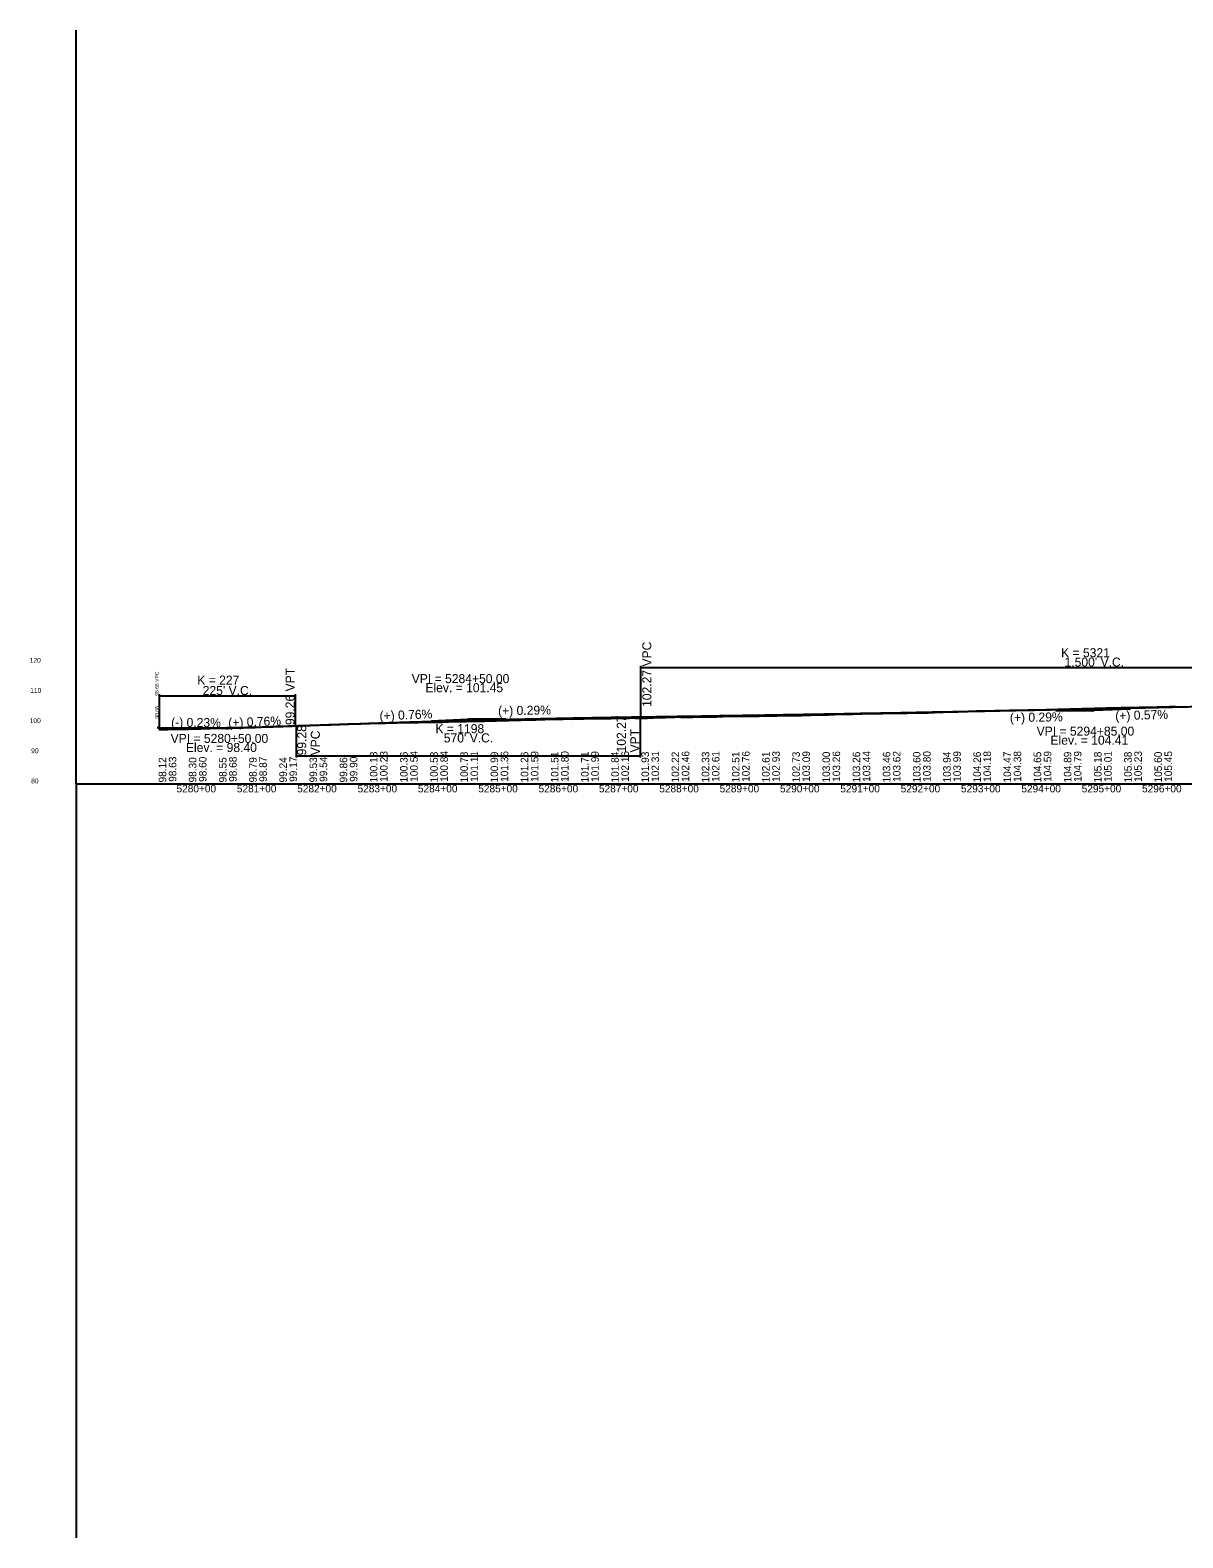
# Model space of a CAD drawing. Extents: x 2121671 to 2169879, y 557274 to 599957.
# Drawn here: x 2157292 to 2159202, y 597457 to 599957 of the extents above; entities that cross this region are included whole.
import ezdxf

# ---------------------------------------------------------------- set-up
doc = ezdxf.new("R2010")
doc.units = 0
for name, color, linetype in [('RD_DDB_ElevTX', 7, 'Continuous'), ('RD_DDB_GradeTX', 7, 'Continuous'), ('RD_DDB_Profile_EX', 7, 'Continuous'), ('RD_DDB_Profile_Lbl', 7, 'Continuous'), ('RD_DDB_Profile_PR', 7, 'Continuous'), ('RD_DDB_StaTX', 7, 'Continuous'), ('RD_DDB_StripGrade', 7, 'Continuous'), ('RD_DDB_VCLbl', 7, 'Continuous'), ('RD_GPK_Profile_Cell', 7, 'Continuous')]:
    doc.layers.add(name, color=color, linetype=linetype)

msp = doc.modelspace()

# ---------------------------------------------------------------- linework, layer by layer
at = {"layer": 'RD_DDB_GradeTX'}
for p, q in [((2158991.3, 598828.7), (2159052.2, 598829.5)), ((2159115.2, 598831.3), (2159054.2, 598829.6)), ((2157556.2, 598800.2), (2157617.2, 598799.5)), ((2157680.2, 598801.8), (2157619.2, 598799.5)), ((2157956.3, 598812.4), (2158017.2, 598814.7)), ((2158080.2, 598815.6), (2158019.2, 598814.7))]:
    msp.add_line(p, q, dxfattribs=at)
for centre in [(2159053.2, 598829.5), (2157504.8, 598800.8), (2157618.2, 598799.5), (2158018.2, 598814.7)]:
    msp.add_circle(centre, 1, dxfattribs=at)
at = {"layer": 'RD_DDB_Profile_EX'}
for points in [[(2158504.8, 598820.3), (2158509.8, 598820.5), (2158514.8, 598820.5), (2158519.8, 598820.6), (2158524.8, 598820.7), (2158529.8, 598820.7), (2158534.8, 598820.8), (2158539.8, 598820.9), (2158544.8, 598820.9), (2158549.8, 598820.9), (2158554.8, 598820.9), (2158559.8, 598820.9), (2158564.8, 598821), (2158569.8, 598821.2), (2158574.8, 598821.4), (2158579.8, 598821.6), (2158584.8, 598821.8), (2158589.8, 598821.9), (2158594.8, 598822), (2158599.8, 598822.2), (2158604.8, 598822.2), (2158609.8, 598822.2), (2158614.8, 598822.3), (2158619.8, 598822.6), (2158624.8, 598822.8), (2158629.8, 598823), (2158634.8, 598823.1), (2158639.8, 598823.2), (2158644.8, 598823.3), (2158649.8, 598823.4), (2158654.8, 598823.5), (2158659.8, 598823.6), (2158664.8, 598823.7), (2158669.8, 598823.8), (2158674.8, 598824.1), (2158679.8, 598824.2), (2158684.8, 598824.2), (2158689.8, 598824.3), (2158694.8, 598824.4), (2158699.8, 598824.5), (2158704.8, 598824.6), (2158709.8, 598824.8), (2158714.8, 598824.7), (2158719.8, 598824.8), (2158724.8, 598825), (2158729.8, 598825), (2158734.8, 598825), (2158739.8, 598825.1), (2158744.8, 598825.1), (2158749.8, 598825.2), (2158754.8, 598825.2), (2158759.8, 598825.3), (2158764.8, 598825.4), (2158769.8, 598825.5), (2158774.8, 598825.6), (2158779.8, 598825.6), (2158784.8, 598825.8), (2158789.8, 598825.9), (2158794.8, 598826.7), (2158799.8, 598826.7), (2158804.8, 598826.8), (2158809.8, 598827), (2158814.8, 598827.1), (2158819.8, 598827.2), (2158824.8, 598827.3), (2158829.8, 598827.4), (2158834.8, 598827.5), (2158839.8, 598827.6), (2158844.8, 598827.8), (2158849.8, 598828), (2158854.8, 598828.3), (2158859.8, 598828.6), (2158864.8, 598828.7), (2158869.8, 598828.8), (2158874.8, 598828.9), (2158879.8, 598829), (2158884.8, 598829), (2158889.8, 598829.1), (2158894.8, 598829.3), (2158899.8, 598829.4), (2158904.8, 598829.6), (2158909.8, 598829.6), (2158914.8, 598829.7), (2158919.8, 598829.9), (2158924.8, 598830), (2158929.8, 598830), (2158934.8, 598830), (2158939.8, 598830.1), (2158944.8, 598830.3), (2158949.8, 598830.5), (2158954.8, 598830.4), (2158959.8, 598830.5), (2158964.8, 598830.6), (2158969.8, 598830.7), (2158974.8, 598830.8), (2158979.8, 598830.9), (2158984.8, 598831), (2158989.8, 598831.2), (2158994.8, 598831.3), (2158999.8, 598831.5), (2159004.8, 598831.7)], [(2159004.8, 598831.7), (2159009.8, 598831.7), (2159014.8, 598831.9), (2159019.8, 598832), (2159024.8, 598832.1), (2159029.8, 598832.2), (2159034.8, 598832.4), (2159039.8, 598832.6), (2159044.8, 598832.7), (2159049.8, 598832.9), (2159054.8, 598833), (2159059.8, 598833.1), (2159064.8, 598833.3), (2159069.8, 598833.4), (2159074.8, 598833.5), (2159079.8, 598833.8), (2159084.8, 598833.8), (2159089.8, 598833.9), (2159094.8, 598834), (2159099.8, 598834.1), (2159104.8, 598834.2), (2159109.8, 598834.3), (2159114.8, 598834.3), (2159119.8, 598834.4), (2159124.8, 598834.5), (2159129.8, 598834.7), (2159134.8, 598834.9), (2159139.8, 598835), (2159144.8, 598835), (2159149.8, 598835), (2159154.8, 598835.1), (2159159.8, 598835.2), (2159164.8, 598835.3), (2159169.8, 598835.5), (2159174.8, 598835.6), (2159179.8, 598835.8), (2159184.8, 598835.9), (2159189.8, 598836), (2159194.8, 598835.6), (2159199.8, 598835.7), (2159204.8, 598836)], [(2157504.8, 598797.9), (2157509.8, 598798), (2157514.8, 598798), (2157519.8, 598798.1), (2157524.8, 598798.2), (2157529.8, 598798.3), (2157534.8, 598798.3), (2157539.8, 598798.4), (2157544.8, 598798.4), (2157549.8, 598798.5), (2157554.8, 598798.5), (2157559.8, 598798.7), (2157564.8, 598798.9), (2157569.8, 598799), (2157574.8, 598799.2), (2157579.8, 598799.4), (2157584.8, 598799.5), (2157589.8, 598799.7), (2157594.8, 598799.8), (2157599.8, 598799.8), (2157604.8, 598799.9), (2157609.8, 598800), (2157614.8, 598800.1), (2157619.8, 598800.2), (2157624.8, 598800.3), (2157629.8, 598800.5), (2157634.8, 598800.6), (2157639.8, 598800.4), (2157644.8, 598800.7), (2157649.8, 598801.1), (2157654.8, 598801.1), (2157659.8, 598801.1), (2157664.8, 598801.2), (2157669.8, 598801.5), (2157674.8, 598801.8), (2157679.8, 598802.2), (2157684.8, 598802.4), (2157689.8, 598802.7), (2157694.8, 598803), (2157699.8, 598803.2), (2157704.8, 598803.3), (2157709.8, 598803.5), (2157714.8, 598803.6), (2157719.8, 598803.7), (2157724.8, 598803.9), (2157729.8, 598804.1), (2157734.8, 598804.4), (2157739.8, 598804.6), (2157744.8, 598804.6), (2157749.8, 598804.7), (2157754.8, 598804.8), (2157759.8, 598804.8), (2157764.8, 598804.9), (2157769.8, 598805.2), (2157774.8, 598805.5), (2157779.8, 598805.5), (2157784.8, 598805.7), (2157789.8, 598805.8), (2157794.8, 598805.9), (2157799.8, 598806), (2157804.8, 598806.3), (2157809.8, 598806.5), (2157814.8, 598806.6), (2157819.8, 598806.8), (2157824.8, 598807), (2157829.8, 598807.1), (2157834.8, 598807.2), (2157839.8, 598807.4), (2157844.8, 598807.6), (2157849.8, 598807.8), (2157854.8, 598808), (2157859.8, 598808.1), (2157864.8, 598808.2), (2157869.8, 598808.4), (2157874.8, 598808.5), (2157879.8, 598808.6), (2157884.8, 598808.7), (2157889.8, 598808.9), (2157894.8, 598809), (2157899.8, 598809.1), (2157904.8, 598809.2), (2157909.8, 598809.3), (2157914.8, 598809.2), (2157919.8, 598809.3), (2157924.8, 598809.4), (2157929.8, 598809.5), (2157934.8, 598809.6), (2157939.8, 598809.8), (2157944.8, 598809.8), (2157949.8, 598809.8), (2157954.8, 598810), (2157959.8, 598810.2), (2157964.8, 598810.1), (2157969.8, 598810.1), (2157974.8, 598810.2), (2157979.8, 598810.3), (2157984.8, 598810.6), (2157989.8, 598810.9), (2157994.8, 598811), (2157999.8, 598810.9), (2158004.8, 598811)], [(2158004.8, 598811), (2158009.8, 598811.1), (2158014.8, 598811.3), (2158019.8, 598811.4), (2158024.8, 598811.5), (2158029.8, 598811.6), (2158034.8, 598811.1), (2158039.8, 598811.9), (2158044.8, 598811.9), (2158049.8, 598812), (2158054.8, 598812.1), (2158059.8, 598812.2), (2158064.8, 598812.4), (2158069.8, 598812.5), (2158074.8, 598812.5), (2158079.8, 598812.6), (2158084.8, 598812.9), (2158089.8, 598813.1), (2158094.8, 598813.2), (2158099.8, 598813.4), (2158104.8, 598813.4), (2158109.8, 598813.6), (2158114.8, 598813.7), (2158119.8, 598813.8), (2158124.8, 598813.8), (2158129.8, 598814.1), (2158134.8, 598814.4), (2158139.8, 598814.5), (2158144.8, 598814.6), (2158149.8, 598814.7), (2158154.8, 598814.8), (2158159.8, 598814.9), (2158164.8, 598814.9), (2158169.8, 598815), (2158174.8, 598815.1), (2158179.8, 598815.3), (2158184.8, 598815.3), (2158189.8, 598815.1), (2158194.8, 598815.3), (2158199.8, 598815.3), (2158204.8, 598815.4), (2158209.8, 598815.6), (2158214.8, 598815.9), (2158219.8, 598816.1), (2158224.8, 598816.2), (2158229.8, 598816.2), (2158234.8, 598816.2), (2158239.8, 598816.3), (2158244.8, 598816.2), (2158249.8, 598816.2), (2158254.8, 598816.3), (2158259.8, 598816.5), (2158264.8, 598816.6), (2158269.8, 598816.7), (2158274.8, 598816.7), (2158279.8, 598816.8), (2158284.8, 598816.9), (2158289.8, 598817), (2158294.8, 598816.8), (2158299.8, 598816.8), (2158304.8, 598816.9), (2158309.8, 598816.9), (2158314.8, 598816.9), (2158319.8, 598817.3), (2158324.8, 598817.4), (2158329.8, 598817.6), (2158334.8, 598817.7), (2158339.8, 598817.8), (2158344.8, 598817.9), (2158349.8, 598818.1), (2158354.8, 598818.3), (2158359.8, 598818.5), (2158364.8, 598818.6), (2158369.8, 598818.5), (2158374.8, 598818.5), (2158379.8, 598818.5), (2158384.8, 598818.5), (2158389.8, 598818.5), (2158394.8, 598818.6), (2158399.8, 598818.7), (2158404.8, 598818.8), (2158409.8, 598819), (2158414.8, 598819.1), (2158419.8, 598819.1), (2158424.8, 598819.1), (2158429.8, 598819.1), (2158434.8, 598819.6), (2158439.8, 598819.6), (2158444.8, 598819.7), (2158449.8, 598819.7), (2158454.8, 598819.7), (2158459.8, 598819.8), (2158464.8, 598819.9), (2158469.8, 598820), (2158474.8, 598820.1), (2158479.8, 598820.1), (2158484.8, 598820), (2158489.8, 598820), (2158494.8, 598820.1), (2158499.8, 598820.2), (2158504.8, 598820.3)]]:
    msp.add_lwpolyline(points, dxfattribs=at)
at = {"layer": 'RD_DDB_Profile_PR'}
for p, q in [((2157504.8, 598800.8), (2157505.7, 598800.8)), ((2157730.7, 598803.8), (2157733.2, 598803.9))]:
    msp.add_line(p, q, dxfattribs=at)
for points in [[(2158303.2, 598818.8), (2158333.2, 598819.2), (2158363.2, 598819.7), (2158393.2, 598820.1), (2158423.2, 598820.6), (2158453.2, 598821.1), (2158483.2, 598821.5), (2158513.2, 598822), (2158543.2, 598822.5), (2158573.2, 598823), (2158603.2, 598823.5), (2158633.2, 598824), (2158663.2, 598824.6), (2158693.2, 598825.1), (2158723.2, 598825.6), (2158753.2, 598826.2), (2158783.2, 598826.8), (2158813.2, 598827.3), (2158843.2, 598827.9), (2158873.2, 598828.5), (2158903.2, 598829.1), (2158933.2, 598829.7), (2158963.2, 598830.3), (2158993.2, 598830.9), (2159023.2, 598831.5), (2159053.2, 598832.2), (2159083.2, 598832.8), (2159113.2, 598833.5), (2159143.2, 598834.1), (2159173.2, 598834.8), (2159203.2, 598835.5), (2159233.2, 598836.2), (2159263.2, 598836.9), (2159293.2, 598837.6), (2159323.2, 598838.3), (2159353.2, 598839), (2159383.2, 598839.7), (2159413.2, 598840.5), (2159443.2, 598841.2), (2159473.2, 598842), (2159503.2, 598842.8), (2159533.2, 598843.5), (2159563.2, 598844.3), (2159593.2, 598845.1), (2159623.2, 598845.9), (2159653.2, 598846.7), (2159683.2, 598847.5), (2159713.2, 598848.3), (2159743.2, 598849.2), (2159773.2, 598850), (2159803.2, 598850.9)], [(2157505.7, 598800.8), (2157510.2, 598800.7), (2157514.7, 598800.7), (2157519.2, 598800.6), (2157523.7, 598800.6), (2157528.2, 598800.6), (2157532.7, 598800.5), (2157537.2, 598800.5), (2157541.7, 598800.5), (2157546.2, 598800.5), (2157550.7, 598800.5), (2157555.2, 598800.5), (2157559.7, 598800.5), (2157564.2, 598800.5), (2157568.7, 598800.5), (2157573.2, 598800.5), (2157577.7, 598800.5), (2157582.2, 598800.5), (2157586.7, 598800.6), (2157591.2, 598800.6), (2157595.7, 598800.6), (2157600.2, 598800.7), (2157604.7, 598800.7), (2157609.2, 598800.8), (2157613.7, 598800.8), (2157618.2, 598800.9), (2157622.7, 598800.9), (2157627.2, 598801), (2157631.7, 598801.1), (2157636.2, 598801.1), (2157640.7, 598801.2), (2157645.2, 598801.3), (2157649.7, 598801.4), (2157654.2, 598801.5), (2157658.7, 598801.6), (2157663.2, 598801.7), (2157667.7, 598801.8), (2157672.2, 598801.9), (2157676.7, 598802), (2157681.2, 598802.1), (2157685.7, 598802.3), (2157690.2, 598802.4), (2157694.7, 598802.5), (2157699.2, 598802.7), (2157703.7, 598802.8), (2157708.2, 598803), (2157712.7, 598803.1), (2157717.2, 598803.3), (2157721.7, 598803.4), (2157726.2, 598803.6), (2157730.7, 598803.8)], [(2157733.2, 598803.9), (2157744.6, 598804.3), (2157756, 598804.7), (2157767.4, 598805.1), (2157778.8, 598805.6), (2157790.2, 598806), (2157801.6, 598806.4), (2157813, 598806.8), (2157824.4, 598807.2), (2157835.8, 598807.5), (2157847.2, 598807.9), (2157858.6, 598808.3), (2157870, 598808.7), (2157881.4, 598809), (2157892.8, 598809.4), (2157904.2, 598809.8), (2157915.6, 598810.1), (2157927, 598810.5), (2157938.4, 598810.8), (2157949.8, 598811.1), (2157961.2, 598811.5), (2157972.6, 598811.8), (2157984, 598812.1), (2157995.4, 598812.4), (2158006.8, 598812.7), (2158018.2, 598813), (2158029.6, 598813.3), (2158041, 598813.6), (2158052.4, 598813.9), (2158063.8, 598814.2), (2158075.2, 598814.5), (2158086.6, 598814.7), (2158098, 598815), (2158109.4, 598815.2), (2158120.8, 598815.5), (2158132.2, 598815.7), (2158143.6, 598816), (2158155, 598816.2), (2158166.4, 598816.5), (2158177.8, 598816.7), (2158189.2, 598816.9), (2158200.6, 598817.1), (2158212, 598817.3), (2158223.4, 598817.5), (2158234.8, 598817.7), (2158246.2, 598817.9), (2158257.6, 598818.1), (2158269, 598818.3), (2158280.4, 598818.5), (2158291.8, 598818.6), (2158303.2, 598818.8)]]:
    msp.add_spline(points, degree=3, dxfattribs=at)
at = {"layer": 'RD_DDB_VCLbl'}
for p, q in [((2158303.2, 598903.4), (2158303.2, 598818.8)), ((2158303.2, 598900.9), (2159803.2, 598900.9)), ((2157505.7, 598856.3), (2157505.7, 598800.8)), ((2157505.7, 598853.8), (2157730.7, 598853.8)), ((2157730.7, 598856.3), (2157730.7, 598803.8)), ((2157733.2, 598751.4), (2157733.2, 598803.9)), ((2158303.2, 598751.4), (2158303.2, 598818.8)), ((2157733.2, 598753.9), (2158303.2, 598753.9))]:
    msp.add_line(p, q, dxfattribs=at)
at = {"layer": 'RD_GPK_Profile_Cell'}
for q in [(2157368.2, 599957.5), (2160768.2, 598707.5), (2157368.2, 597457.5)]:
    msp.add_line((2157368.2, 598707.5), q, dxfattribs=at)

# ---------------------------------------------------------------- texts
at = {"layer": 'RD_DDB_ElevTX'}
for s, p in [('120', (2157291, 598908.5)), ('110', (2157291.8, 598858.5)), ('100', (2157291, 598808.5)), ('90', (2157293.4, 598758.5)), ('80', (2157293.4, 598708.5))]:
    msp.add_text(s, height=8, dxfattribs=at).set_placement(p)
at = {"layer": 'RD_DDB_GradeTX'}
for s, rotation, p in [('(+) 0.76%', 2.1825, (2157871, 598813)), ('(+) 0.29%', 0.8206, (2158067.3, 598821.5)), ('(+) 0.29%', 0.8206, (2158915.4, 598810.1)), ('(+) 0.57%', 1.6278, (2159090.1, 598813.1)), ('(-) 0.23%', 359.3411, (2157525.3, 598802.5)), ('(+) 0.76%', 2.1825, (2157620.3, 598801.6))]:
    msp.add_text(s, height=15, rotation=rotation, dxfattribs=at).set_placement(p)
at = {"layer": 'RD_DDB_Profile_Lbl'}
for s, p in [('VPI = 5284+50.00', (2157924.1, 598874.7)), ('Elev. = 101.45', (2157946.7, 598859.7)), ('VPI = 5294+85.00', (2158959.6, 598787.6)), ('VPI = 5280+50.00', (2157524.5, 598775.5)), ('Elev. = 98.40', (2157549.9, 598760.5)), ('Elev. = 104.41', (2158982.6, 598772.6))]:
    msp.add_text(s, height=15, dxfattribs=at).set_placement(p)
msp.add_text('98.66', height=6, rotation=90, dxfattribs=at).set_placement((2157504.8, 598815.8))
at = {"layer": 'RD_DDB_StaTX'}
for s, p in [('5280+00', (2157534.3, 598693.6)), ('5281+00', (2157634.3, 598693.6)), ('5282+00', (2157734.3, 598693.6)), ('5283+00', (2157834.3, 598693.6)), ('5284+00', (2157934.3, 598693.6)), ('5285+00', (2158034.3, 598693.6)), ('5286+00', (2158134.3, 598693.6)), ('5287+00', (2158234.3, 598693.6)), ('5288+00', (2158334.3, 598693.6)), ('5289+00', (2158434.3, 598693.6)), ('5290+00', (2158534.3, 598693.6)), ('5291+00', (2158634.3, 598693.6)), ('5292+00', (2158734.3, 598693.6)), ('5293+00', (2158834.3, 598693.6)), ('5294+00', (2158934.3, 598693.6)), ('5295+00', (2159034.3, 598693.6)), ('5296+00', (2159134.3, 598693.6))]:
    msp.add_text(s, height=12.5, dxfattribs=at).set_placement(p)
at = {"layer": 'RD_DDB_StripGrade'}
for s, height, p in [('102.27 VPC', 15, (2158321.2, 598835.3)), ('98.66 VPC', 6, (2157504.7, 598853.8)), ('99.26 VPT', 15, (2157730, 598805.2)), ('99.28 ', 15, (2157749.3, 598754.9)), ('102.27 ', 15, (2158278.9, 598759.8)), ('VPC', 15, (2157771.8, 598754.9)), ('VPT', 15, (2158301.4, 598759.8)), ('98.12', 12.5, (2157517.2, 598710)), ('98.63', 12.5, (2157534, 598711)), ('98.30', 12.5, (2157567.2, 598710)), ('98.60', 12.5, (2157584, 598711)), ('98.55', 12.5, (2157617.2, 598710)), ('98.68', 12.5, (2157634, 598711)), ('98.79', 12.5, (2157667.2, 598710)), ('98.87', 12.5, (2157684, 598711)), ('99.24', 12.5, (2157717.2, 598710)), ('99.17', 12.5, (2157734, 598711)), ('99.53', 12.5, (2157767.2, 598710)), ('99.54', 12.5, (2157784, 598711)), ('99.86', 12.5, (2157817.2, 598710)), ('99.90', 12.5, (2157834, 598711)), ('100.18', 12.5, (2157867.2, 598710)), ('100.23', 12.5, (2157884, 598711)), ('100.36', 12.5, (2157917.2, 598710)), ('100.54', 12.5, (2157934, 598711)), ('100.53', 12.5, (2157967.2, 598710)), ('100.84', 12.5, (2157984, 598711)), ('100.78', 12.5, (2158017.2, 598710)), ('101.11', 12.5, (2158034, 598711)), ('100.99', 12.5, (2158067.2, 598710)), ('101.36', 12.5, (2158084, 598711)), ('101.26', 12.5, (2158117.2, 598710)), ('101.59', 12.5, (2158134, 598711)), ('101.51', 12.5, (2158167.2, 598710)), ('101.80', 12.5, (2158184, 598711)), ('101.71', 12.5, (2158217.2, 598710)), ('101.99', 12.5, (2158234, 598711)), ('101.84', 12.5, (2158267.2, 598710)), ('102.16', 12.5, (2158284, 598711)), ('101.93', 12.5, (2158317.2, 598710)), ('102.31', 12.5, (2158334, 598711)), ('102.22', 12.5, (2158367.2, 598710)), ('102.46', 12.5, (2158384, 598711)), ('102.33', 12.5, (2158417.2, 598710)), ('102.61', 12.5, (2158434, 598711)), ('102.51', 12.5, (2158467.2, 598710)), ('102.76', 12.5, (2158484, 598711)), ('102.61', 12.5, (2158517.2, 598710)), ('102.93', 12.5, (2158534, 598711)), ('102.73', 12.5, (2158567.2, 598710)), ('103.09', 12.5, (2158584, 598711)), ('103.00', 12.5, (2158617.2, 598710)), ('103.26', 12.5, (2158634, 598711)), ('103.26', 12.5, (2158667.2, 598710)), ('103.44', 12.5, (2158684, 598711)), ('103.46', 12.5, (2158717.2, 598710)), ('103.62', 12.5, (2158734, 598711)), ('103.60', 12.5, (2158767.2, 598710)), ('103.80', 12.5, (2158784, 598711)), ('103.94', 12.5, (2158817.2, 598710)), ('103.99', 12.5, (2158834, 598711)), ('104.26', 12.5, (2158867.2, 598710)), ('104.18', 12.5, (2158884, 598711)), ('104.47', 12.5, (2158917.2, 598710)), ('104.38', 12.5, (2158934, 598711)), ('104.65', 12.5, (2158967.2, 598710)), ('104.59', 12.5, (2158984, 598711)), ('104.89', 12.5, (2159017.2, 598710)), ('104.79', 12.5, (2159034, 598711)), ('105.18', 12.5, (2159067.2, 598710)), ('105.01', 12.5, (2159084, 598711)), ('105.38', 12.5, (2159117.2, 598710)), ('105.23', 12.5, (2159134, 598711)), ('105.60', 12.5, (2159167.2, 598710)), ('105.45', 12.5, (2159184, 598711))]:
    msp.add_text(s, height=height, rotation=90, dxfattribs=at).set_placement(p)
at = {"layer": 'RD_DDB_VCLbl'}
for s, p in [('K = 5321', (2159000.1, 598917.6)), ("1,500' V.C.", (2159005.9, 598902.1)), ('K = 227', (2157568.7, 598872.2)), ("225' V.C.", (2157577.7, 598855)), ('K = 1198', (2157963.3, 598791.7)), ("570' V.C.", (2157977.2, 598776.4))]:
    msp.add_text(s, height=15, dxfattribs=at).set_placement(p)
at = {"layer": 'RD_GPK_Profile_Cell'}
for s, p in [('I95', (2157368.2, 598711.8)), ('P_C_NBSPLIT2', (2157368.2, 598711.2)), ('527800.000000', (2157368.2, 598710.6)), ('80', (2157368.2, 598710)), ('50', (2157368.2, 598709.3)), ('10', (2157368.2, 598708.7)), ('NOGAP', (2157368.2, 598708.1))]:
    msp.add_text(s, height=0.208, dxfattribs=at).set_placement(p)

doc.saveas('drawing.dxf')
